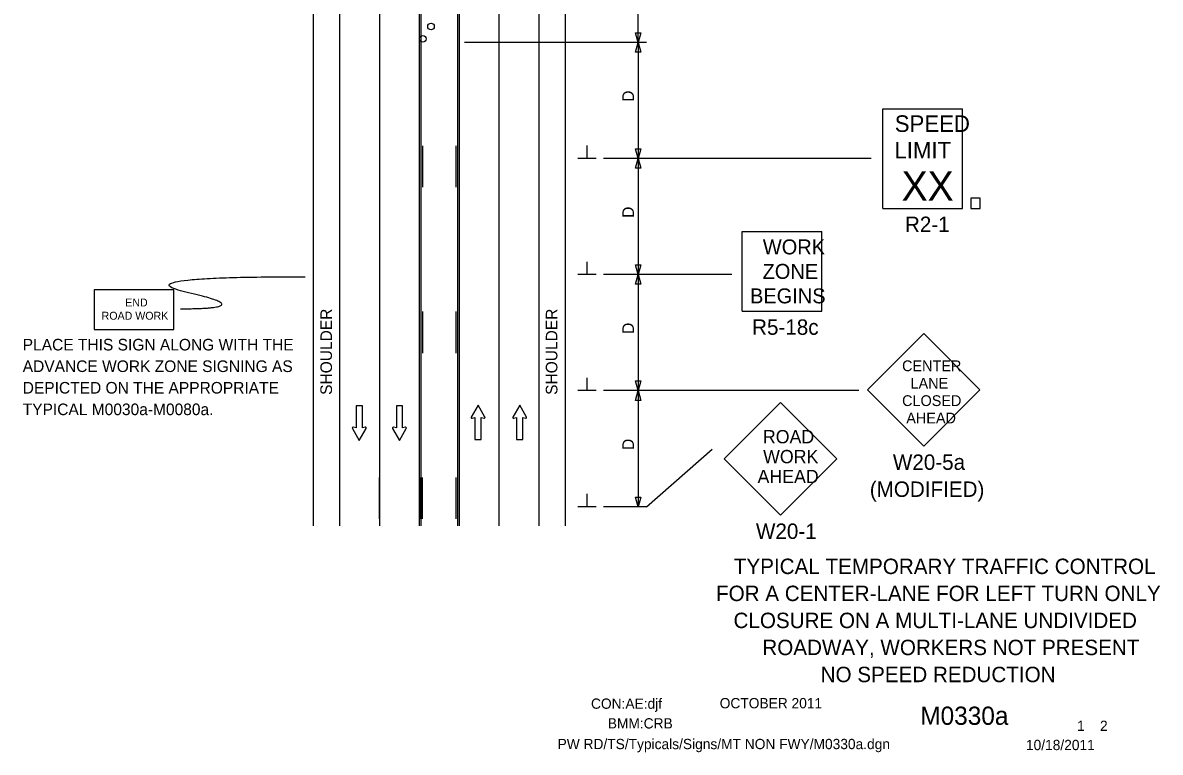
# Model space of a CAD drawing. Extents: x 16739 to 18482, y 7218 to 8206.
# Drawn here: x 16748 to 17434, y 7218 to 7658 of the extents above; entities that cross this region are included whole.
import ezdxf

# ---------------------------------------------------------------- set-up
doc = ezdxf.new("R2010")
doc.units = 0
for name, color, linetype in [('ALI_LEGAL_EX', 7, 'Continuous'), ('BORDER_SIGNAL_WO', 7, 'Continuous'), ('MT_SCRATCH_LEVEL_E', 7, 'Continuous'), ('PAVT_EDGE_EX', 7, 'Continuous'), ('TRAFFIC_SIGNS_PR', 7, 'Continuous'), ('TYPICAL_TEXT_DIMEN_PR', 7, 'Continuous')]:
    doc.layers.add(name, color=color, linetype=linetype)

msp = doc.modelspace()

# ---------------------------------------------------------------- linework, layer by layer
at = {"layer": 'ALI_LEGAL_EX'}
for points in [[(16963.15, 7583.87), (16963.15, 7558.87)], [(17035.15, 7583.87), (17035.15, 7558.87)], [(16963.15, 7483.87), (16963.15, 7458.87)], [(17035.15, 7483.87), (17035.15, 7458.87)], [(16963.15, 7358.87), (16963.15, 7383.87)], [(17035.15, 7383.87), (17035.15, 7358.87)]]:
    msp.add_lwpolyline(points, dxfattribs=at)
at = {"layer": 'MT_SCRATCH_LEVEL_E'}
for p, q in [((17022.59, 7427.51), (17018.48, 7420.27)), ((17022.59, 7427.51), (17018.48, 7420.27)), ((17026.74, 7420.27), (17022.59, 7427.51)), ((17026.74, 7420.27), (17022.59, 7427.51)), ((17047.68, 7427.51), (17043.57, 7420.27)), ((17047.68, 7427.51), (17043.57, 7420.27)), ((17051.83, 7420.27), (17047.68, 7427.51)), ((17051.83, 7420.27), (17047.68, 7427.51)), ((16952.82, 7427.05), (16949.08, 7427.05)), ((16949.08, 7427.05), (16949.08, 7413.79)), ((16952.82, 7427.05), (16949.08, 7427.05)), ((16949.08, 7427.05), (16949.08, 7413.79)), ((16952.82, 7413.79), (16952.82, 7427.05)), ((16952.82, 7413.79), (16952.82, 7427.05)), ((16977.08, 7427.05), (16973.34, 7427.05)), ((16973.34, 7427.05), (16973.34, 7413.79)), ((16977.08, 7427.05), (16973.34, 7427.05)), ((16973.34, 7427.05), (16973.34, 7413.79)), ((16977.08, 7413.79), (16977.08, 7427.05)), ((16977.08, 7413.79), (16977.08, 7427.05)), ((16949.08, 7413.79), (16947.3, 7414.11)), ((16949.08, 7413.79), (16947.3, 7414.11)), ((16954.6, 7414.11), (16952.82, 7413.79)), ((16954.6, 7414.11), (16952.82, 7413.79)), ((16973.34, 7413.79), (16971.56, 7414.11)), ((16973.34, 7413.79), (16971.56, 7414.11)), ((16978.86, 7414.11), (16977.08, 7413.79)), ((16978.86, 7414.11), (16977.08, 7413.79)), ((17018.96, 7419.59), (17020.74, 7419.9)), ((17018.96, 7419.59), (17020.74, 7419.9)), ((17020.74, 7419.9), (17020.74, 7406.65)), ((17020.74, 7419.9), (17020.74, 7406.65)), ((17024.48, 7406.65), (17024.48, 7419.9)), ((17024.48, 7419.9), (17026.26, 7419.59)), ((17024.48, 7406.65), (17024.48, 7419.9)), ((17024.48, 7419.9), (17026.26, 7419.59)), ((17044.05, 7419.59), (17045.83, 7419.9)), ((17044.05, 7419.59), (17045.83, 7419.9)), ((17045.83, 7419.9), (17045.83, 7406.65)), ((17045.83, 7419.9), (17045.83, 7406.65)), ((17049.57, 7406.65), (17049.57, 7419.9)), ((17049.57, 7419.9), (17051.35, 7419.59)), ((17049.57, 7406.65), (17049.57, 7419.9)), ((17049.57, 7419.9), (17051.35, 7419.59)), ((16946.82, 7413.43), (16950.97, 7406.18)), ((16946.82, 7413.43), (16950.97, 7406.18)), ((16950.97, 7406.18), (16955.08, 7413.43)), ((16950.97, 7406.18), (16955.08, 7413.43)), ((16971.08, 7413.43), (16975.23, 7406.18)), ((16971.08, 7413.43), (16975.23, 7406.18)), ((16975.23, 7406.18), (16979.34, 7413.43)), ((16975.23, 7406.18), (16979.34, 7413.43)), ((17020.74, 7406.65), (17024.48, 7406.65)), ((17020.74, 7406.65), (17024.48, 7406.65)), ((17045.83, 7406.65), (17049.57, 7406.65)), ((17045.83, 7406.65), (17049.57, 7406.65))]:
    msp.add_line(p, q, dxfattribs=at)
for centre, start, end in [((16947.23, 7413.65), 80.03619, 209.77312), ((16947.23, 7413.65), 80.03619, 209.77312), ((16954.67, 7413.65), 330.42484, 99.96381), ((16954.67, 7413.65), 330.42484, 99.96381), ((16971.49, 7413.65), 80.03619, 209.77312), ((16971.49, 7413.65), 80.03619, 209.77312), ((16978.93, 7413.65), 330.42484, 99.96381), ((16978.93, 7413.65), 330.42484, 99.96381), ((17018.89, 7420.05), 150.42484, 279.96381), ((17018.89, 7420.05), 150.42484, 279.96381), ((17026.33, 7420.05), 260.03619, 29.77312), ((17026.33, 7420.05), 260.03619, 29.77312), ((17043.98, 7420.05), 150.42484, 279.96381), ((17043.98, 7420.05), 150.42484, 279.96381), ((17051.42, 7420.05), 260.03619, 29.77312), ((17051.42, 7420.05), 260.03619, 29.77312)]:
    msp.add_arc(centre, 0.463, start, end, dxfattribs=at)
at = {"layer": 'PAVT_EDGE_EX'}
for p, q in [((16923.15, 8183.87), (16923.15, 7354.69)), ((16939.15, 8183.87), (16939.15, 7354.69)), ((16963.15, 8183.87), (16963.15, 7354.69)), ((16987.15, 8183.87), (16987.15, 7354.69)), ((16988.15, 8183.87), (16988.15, 7354.69)), ((17010.15, 8183.87), (17010.15, 7354.69)), ((17011.15, 8183.87), (17011.15, 7354.69)), ((17035.15, 8183.87), (17035.15, 7354.69)), ((17059.15, 8183.87), (17059.15, 7354.69)), ((17075.15, 8183.87), (17075.15, 7354.69))]:
    msp.add_line(p, q, dxfattribs=at)
for points in [[(16989.15, 7583.87), (16989.15, 7558.87)], [(17009.15, 7583.87), (17009.15, 7558.87)], [(16989.15, 7483.87), (16989.15, 7458.87)], [(17009.15, 7483.87), (17009.15, 7458.87)], [(16963.15, 7358.87), (16963.15, 7383.87)], [(16988.15, 7358.87), (16988.15, 7383.87)], [(16989.15, 7358.87), (16989.15, 7383.87)], [(17009.15, 7383.87), (17009.15, 7358.87)]]:
    msp.add_lwpolyline(points, dxfattribs=at)
at = {"layer": 'TRAFFIC_SIGNS_PR'}
for p, q in [((17266.62, 7606.12), (17314.62, 7606.12)), ((17266.62, 7546.12), (17266.62, 7606.12)), ((17314.62, 7546.12), (17314.62, 7606.12)), ((17266.62, 7546.12), (17314.62, 7546.12)), ((17181.79, 7484.14), (17181.79, 7532.14)), ((17181.79, 7532.14), (17229.79, 7532.14)), ((17229.79, 7484.14), (17229.79, 7532.14)), ((17181.79, 7484.14), (17229.79, 7484.14)), ((17291.28, 7470.58), (17257.33, 7436.64)), ((17325.22, 7436.64), (17291.28, 7470.58)), ((17257.33, 7436.64), (17291.28, 7402.7)), ((17291.28, 7402.7), (17325.22, 7436.64)), ((17204.91, 7428.93), (17170.97, 7394.99)), ((17238.86, 7394.99), (17204.91, 7428.93)), ((17170.97, 7394.99), (17204.91, 7361.05)), ((17204.91, 7361.05), (17238.86, 7394.99))]:
    msp.add_line(p, q, dxfattribs=at)
for points in [[(17319.64, 7546.12), (17325.23, 7546.12), (17325.23, 7552.29), (17319.64, 7552.29)], [(16791.12, 7473.01), (16839.12, 7473.01), (16839.12, 7497.01), (16791.12, 7497.01)]]:
    msp.add_lwpolyline(points, close=True, dxfattribs=at)
for centre in [(16994.22, 7655.79), (16989.25, 7648.28)]:
    msp.add_circle(centre, 2, dxfattribs=at)
msp.add_open_spline([(16843.28, 7485.55), (16890.52, 7485.55), (16805.5, 7504.9), (16918.31, 7504.9)], degree=2, dxfattribs=at)
at = {"layer": 'TYPICAL_TEXT_DIMEN_PR'}
for p, q in [((17119.15, 7646.17), (17119.15, 7680.36)), ((17119.15, 7646.17), (17117.58, 7652.03)), ((17117.58, 7652.03), (17119.15, 7652.03)), ((17119.15, 7652.03), (17120.72, 7652.03)), ((17120.72, 7652.03), (17119.15, 7646.17)), ((17124.15, 7646.17), (17014.45, 7646.17)), ((17117.58, 7640.31), (17119.15, 7646.17)), ((17119.15, 7640.31), (17117.58, 7640.31)), ((17119.15, 7646.17), (17119.15, 7576.17)), ((17119.15, 7646.17), (17120.72, 7640.31)), ((17120.72, 7640.31), (17119.15, 7640.31)), ((17119.15, 7601.04), (17119.15, 7597.27)), ((17088.28, 7576.17), (17088.28, 7583.95)), ((17119.15, 7576.17), (17117.58, 7582.03)), ((17117.58, 7582.03), (17119.15, 7582.03)), ((17119.15, 7582.03), (17120.72, 7582.03)), ((17120.72, 7582.03), (17119.15, 7576.17)), ((17093.9, 7576.17), (17082.65, 7576.17)), ((17259.59, 7576.17), (17098.15, 7576.17)), ((17117.58, 7570.31), (17119.15, 7576.17)), ((17119.15, 7576.17), (17119.15, 7506.17)), ((17119.15, 7576.17), (17120.72, 7570.31)), ((17119.15, 7570.31), (17117.58, 7570.31)), ((17120.72, 7570.31), (17119.15, 7570.31)), ((17088.28, 7506.17), (17088.28, 7513.95)), ((17119.15, 7506.17), (17117.58, 7512.03)), ((17117.58, 7512.03), (17119.15, 7512.03)), ((17119.15, 7512.03), (17120.72, 7512.03)), ((17120.72, 7512.03), (17119.15, 7506.17)), ((17093.9, 7506.17), (17082.65, 7506.17)), ((17175.55, 7506.17), (17098.15, 7506.17)), ((17117.58, 7500.31), (17119.15, 7506.17)), ((17119.15, 7506.17), (17119.15, 7436.17)), ((17119.15, 7506.17), (17120.72, 7500.31)), ((17119.15, 7500.31), (17117.58, 7500.31)), ((17120.72, 7500.31), (17119.15, 7500.31)), ((17088.28, 7436.17), (17088.28, 7443.95)), ((17119.15, 7436.17), (17117.58, 7442.03)), ((17117.58, 7442.03), (17119.15, 7442.03)), ((17119.15, 7442.03), (17120.72, 7442.03)), ((17120.72, 7442.03), (17119.15, 7436.17)), ((17093.9, 7436.17), (17082.65, 7436.17)), ((17252.08, 7436.17), (17098.15, 7436.17)), ((17117.58, 7430.31), (17119.15, 7436.17)), ((17119.15, 7436.17), (17119.15, 7366.17)), ((17119.15, 7436.17), (17120.72, 7430.31)), ((17119.15, 7430.31), (17117.58, 7430.31)), ((17120.72, 7430.31), (17119.15, 7430.31)), ((17124.15, 7366.17), (17163.83, 7400.91)), ((17088.28, 7366.17), (17088.28, 7373.95)), ((17093.9, 7366.17), (17082.65, 7366.17)), ((17124.15, 7366.17), (17098.15, 7366.17)), ((17119.15, 7366.17), (17117.58, 7372.03)), ((17117.58, 7372.03), (17119.15, 7372.03)), ((17119.15, 7372.03), (17120.72, 7372.03)), ((17120.72, 7372.03), (17119.15, 7366.17))]:
    msp.add_line(p, q, dxfattribs=at)

# ---------------------------------------------------------------- texts
at = {"layer": 'BORDER_SIGNAL_WO'}
for s, height, p in [('TYPICAL TEMPORARY TRAFFIC CONTROL', 9.3, (17176.8, 7325.56)), ('FOR A CENTER-LANE FOR LEFT TURN ONLY', 9.3, (17166.08, 7309.26)), ('CLOSURE ON A MULTI-LANE UNDIVIDED', 9.3, (17176.61, 7292.96)), ('ROADWAY, WORKERS NOT PRESENT', 9.3, (17194, 7276.66)), ('NO SPEED REDUCTION', 9.3, (17229.13, 7260.36)), ('CON:AE:djf', 6.2, (17090.69, 7244.31)), ('    OCTOBER 2011    ', 6.2, (17159.08, 7244.59)), ('    M0330a   ', 11, (17272.86, 7234.63)), ('BMM:CRB   ', 6.2, (17100.81, 7232.42)), (' 1    2 ', 6.2, (17381.45, 7230.95)), ('PW RD/TS/Typicals/Signs/MT NON FWY/M0330a.dgn    ', 6.2, (17070.55, 7219.96)), ('10/18/2011    ', 6.2, (17352.93, 7219.38))]:
    msp.add_text(s, height=height, dxfattribs=at).set_placement(p)
at = {"layer": 'TRAFFIC_SIGNS_PR'}
for s, height, p in [('SPEED', 10, (17273.83, 7592.2)), ('LIMIT', 10, (17273.63, 7576.2)), ('XX', 17.538, (17278.01, 7550.82)), ('R2-1', 9.3, (17279.97, 7531.82)), ('WORK', 9.021, (17194.29, 7518.35)), ('ZONE', 9.021, (17194.14, 7503.59)), ('BEGINS', 9.021, (17186.55, 7488.82)), ('END', 4.789, (16809.87, 7486.92)), ('ROAD WORK', 4.789, (16795.63, 7478.94)), ('R5-18c', 9.3, (17187.81, 7469.84)), ('PLACE THIS SIGN ALONG WITH THE', 7, (16748.06, 7460.4)), ('ADVANCE WORK ZONE SIGNING AS', 7, (16748.06, 7447.4)), ('CENTER', 6.5, (17278.25, 7447.89)), ('DEPICTED ON THE APPROPRIATE', 7, (16748.06, 7434.4)), ('LANE', 6.5, (17283.34, 7437.39)), ('TYPICAL M0030a-M0080a.', 7, (16748.06, 7421.4)), ('CLOSED', 6.5, (17278.25, 7426.89)), ('AHEAD', 6.5, (17280.78, 7416.39)), ('ROAD', 8, (17194.34, 7404.41)), ('WORK', 8, (17194.48, 7392.41)), ('W20-5a', 9.3, (17272.7, 7388.4)), ('AHEAD', 8, (17191.11, 7380.41)), ('(MODIFIED)', 9.3, (17258.77, 7372.1)), ('W20-1', 9.3, (17190.13, 7346.75))]:
    msp.add_text(s, height=height, dxfattribs=at).set_placement(p)
at = {"layer": 'TYPICAL_TEXT_DIMEN_PR'}
for s, p in [('D', (17116.59, 7610.39)), ('D', (17116.59, 7540.39)), ('SHOULDER', (16934.53, 7433.62)), ('SHOULDER', (17070.43, 7433.62)), ('D', (17116.59, 7470.39)), ('D', (17116.59, 7400.39))]:
    msp.add_text(s, height=7, rotation=90, dxfattribs=at).set_placement(p)

doc.saveas('drawing.dxf')
